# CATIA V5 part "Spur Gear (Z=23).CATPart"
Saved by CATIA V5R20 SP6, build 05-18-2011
Part number: Spur Gear (Z=23)
Bounding box of the stored display mesh (mm): x 0 to 10, y -24.981 to 24.981, z -24.855 to 24.99
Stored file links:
  E:\#01 CATIA Lecture Materials\#06 DMU\#10 Kinematics Joints\#002 Gear Joint(Spur Gear)\Spur Gear (Z=23).CATPart
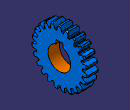
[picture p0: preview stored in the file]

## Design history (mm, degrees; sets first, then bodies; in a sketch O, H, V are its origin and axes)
Parameters
  a = 20 deg
  m = 2 mm
  Z = 23
  rp = 23 mm {= m * Z / 2}
  ra = 25 mm {= rp + m}
  rb = 21.6129 mm {= rp * cos( a  )}
  rf = 20.5 mm {= rp -1.25 * m}
  rc = 0.76 mm {= m * 0.38}
  c = 0.115855 {= sqrt( 1 / ( cos( a ) * cos( a ) ) - 1 ) / PI}
  phi = 4.767 deg
Set1 "Reference Data"
  Point1 "Center Point": (0, 0, 0)
  Line1 "Axis (X Direction)": type PtDir, RefPoint Point1, Direction yz-plane, Start 0, End 20
  Point2 "Involute Curve Point_01": (0, 0, 21.6129)
  Point3 "Involute Curve Point_02": (0, 0.2212, 22.6533)
  Point4 "Involute Curve Point_03": (0, 1.7175, 25.4672)
  Point5 "Involute Curve Point_04": (0, 5.5122, 29.1832)
  Point6 "Involute Curve Point_05": (0, 12.1623, 32.5091)
  Curve1 "Involute Curve": Elements (Point2; Point3; Point4; Point5; Point6)
  Extrapol1: ToExtrapol Point2, Support Curve1, Length 4 {= m * 2}
  Rotate1: ToTransfor Extrapol1, Axis Line1, Angle 4.767 {= phi}
  Circle1: type CtrRad, Start 0, End 180, Center Point1, Support yz-plane, Radius 25 {= ra}, FirstDirection (0, 1, 0)
  Circle2: type CtrRad, Start 0, End 180, Center Point1, Support yz-plane, Radius 20.5 {= rf}, FirstDirection (0, 1, 0)
  Corner1: Element1 Rotate1, Element2 Circle2, Radius 0.76 {= rc}
  Set2 "Corner Operation Body"
    Sketch1 on yz-plane, origin (0, 0, 0), H (0, 1, 0), V (0, 0, 1)
      projected curve E1 from edge of Rotate1
      projected curve E2 from edge of Rotate1
      projected curve E3 from edge of Rotate1
      point P1 (-1.9152, 17.5392)
      projected arc E4 centre (0, 0) radius 20.5 from (20.5, 0) to (-20.5, 0) ccw from Circle2
      projected arc E5 centre (0, 0) radius 20.5 from (-1.831, 20.4181) to (-2.4793, 20.3495) ccw from Circle2
      projected arc E6 centre (0, 0) radius 20.5 from (-2.4793, 20.3495) to (-20.5, 0) ccw from Circle2
      point P3 (20.5, 0)
      arc A1 centre (-2.5712, 21.1039) radius 0.76 from (-1.8115, 21.0817) to (-2.4793, 20.3495) cw
      radius A1 = 0.76 {= rc}
      coincidence: E1 P1, E4 P3
      tangency: A1 E1, A1 E4
    Extrude1: Element1 Rotate1, Lim1 5, Lim2 5, Direction yz-plane
    Extrude2: Element1 Circle2, Lim1 5, Lim2 5, Direction yz-plane
    Intersect1: ToIntersect1 Extrude1, ToIntersect2 yz-plane
    Intersect2: ToIntersect1 Extrude2, ToIntersect2 yz-plane
    Corner2: Element1 Intersect1, Element2 Intersect2, Radius 0.76 {= rc}
  Plane1 "Plane.1(ZX Plane Rotate=9deg)": type Angle, RefPlane zx-plane, Direction Line1, Angle 7.8261 {= 180deg / Z}
  Symmetry1: ToTransfor Corner1, Reference Plane1
  Split1: ToCut Rotate1, Cutting (Circle1; Corner1)
  Symmetry2: ToTransfor Split1, Reference zx-plane
  Point7: type OnCurve, Support Symmetry2, Ratio 1
  Point8: type OnCurve, Support Split1, Ratio 1
  Point9: type OnCurve, Support Corner1, Ratio 1
  Point10: type OnCurve, Support Symmetry1, Ratio 1
  Circle3: type 2PointsRad, Start 0, End 180, FirstPoint Point8, SecondPoint Point7, Support yz-plane, Radius 25 {= ra}
  Circle4: type 2PointsRad, Start 0, End 180, FirstPoint Point9, SecondPoint Point10, Support yz-plane, Radius 20.5 {= rf}
  Join1: Elements (Symmetry2; Circle3; Split1; Corner1; Circle4; Symmetry1)
  CircPattern1: of Join1, instances 23 {= Z}, angular step 15.6522 {= 360.0*1 deg/CircPattern1.AngularNumber}, axis from Line1
  Join2: Elements (Join1; CircPattern1)
Body1 (main body)
  Body2 "Spur Gear Body"
    Pad1: profile Join2, length 10
    Sketch2 on zx-plane, origin (0, 0, 0), H (-1, 0, 0), V (0, 0, 1)
      axis line L1 (0, 0) -> (6.502, 0)
      line L2 (0, 0) -> (0, 24)
      line L3 (-1, 25) -> (-9, 25)
      line L4 (-10, 24) -> (-10, 0)
      point P2 (-10, 0)
      line L5 (-10, 0) -> (0, 0)
      line L6 (-9, 25) -> (-10, 24)
      point P3 (-10, 24)
      line L7 (-1, 25) -> (0, 24)
      point P4 (0, 24)
      construction line L8 (-10, 24) -> (0, 24)
      distance H L3 = 25 {= ra}
      distance L2 L4 = 10 {= Pad1.FirstLimit.Length}
      angle L2 L7 = 45 {= Sketch2.angle(L6 L4)}
      angle L6 L4 = 45
      distance L3 L8 = 1
      horizontal: L1 H, L3 H, L5 H, L8 H
      vertical: L2 V, L4 V
      coincidence: P2 H, P3 L4, P4 L2, P3 L6, P4 L7
    Groove1: profile Sketch2, axis Sketch2.L1, angle 360
  Assemble1: tool Body2
  Body3 "Key Hole Body"
    Sketch3 on yz-plane, origin (0, 0, 0), H (0, 1, 0), V (0, 0, 1)
      arc A1 centre (0, 0) radius 10 from (-3, 9.5394) to (3, 9.5394) ccw
      line L1 (-3, 12.8) -> (3, 12.8)
      line L2 (3, 12.8) -> (3, 9.5394)
      line L3 (-3, 9.5394) -> (-3, 12.8)
      radius A1 = 10
      distance L3 L2 = 6
      distance L1 A1 = 22.8
      horizontal: L1 H
      vertical: L2 V, L3 V
      symmetry: L3 L2 V
    Pad2: profile Sketch3, direction (1, 0, 0), length 10 {= Pad1.FirstLimit.Length}
  Remove1: tool Body3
